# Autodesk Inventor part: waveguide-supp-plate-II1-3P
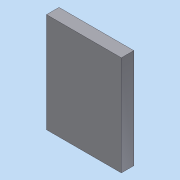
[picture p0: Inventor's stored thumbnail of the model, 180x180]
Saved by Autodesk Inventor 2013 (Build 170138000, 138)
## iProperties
Created: 2012-05
Part Number: waveguide-supp-plate-II1-3P
Material: Edelstahl
Document SubType Name: Modeling
Designer: Henneborn
Description: WAVEGUIDE SUPPORT PLATE II
Mass: 794.445 g
Surface Area: 200 cm^2
Volume: 98.3224 cm^3
Density: 8.08 g/cm^3
Rohmasse: 4" x 3" x 0,125"
Author: vm
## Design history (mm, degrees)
sketch "Sketch1"
  geometry: L1 (-38.1, -50.8)-(38.1, -50.8); L2 (38.1, -50.8)-(38.1, 50.8); L3 (38.1, 50.8)-(-38.1, 50.8); L4 (-38.1, 50.8)-(-38.1, -50.8); 3 further points
  constraints: 8 end point, 2 midpoint, 2 parallel, 1 horizontal, 1 horizontal alignment, 1 perpendicular, 1 vertical alignment
  dimensions: "d0" = 76.2 distance of L1.start L1.end; "d1" = 101.6 distance of L3.end L1.start
extrude "Extrusion1" new body sketch "Sketch1" distance "d2" = 12.7; taper "d3" = 0 deg
body "Solid1"
